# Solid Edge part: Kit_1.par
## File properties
Sűrűség: 0,000 kg/m^3
Pontosság: 0,990
Author: bmolnar
Last saved by: bmolnar
Revision: 77
Username: bmolnar
Dokumentum tartalom típus: 0
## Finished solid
Body 1: solid body, 30 faces, 47 edges, 37 vertices.
  Faces by surface: plane 12, cylinder 10, cone 6, torus 2
  Edges by curve: circle 29, line 18
Bounding box of the edges (mm; curved faces can reach further): 29.400 x 28.800 x 3.400, from (-14.6832, -13.45, 54.8) to (14.7168, 15.3498, 58.2).
Cylindrical faces by radius (mm): R1 x2, R1.8 x2, R5.24 x1, R5.7 x1, R8.75 x1, R12.9833 x1, R13.45 x1, R14.7 x1
Conical faces (half-angle, radius in mm at the cone's reference point): 14 deg R5.12 x1, 14 deg R5.3801 x1, 17 deg R5.12 x1, 45 deg R5.85 x1, 45 deg R8.5 x1, 87 deg R5.1371 x1
Toroidal faces (ring radius, tube radius in mm): R5.6606 r0.18 x1, R9.15 r0.4 x1
Planar faces by outward normal: +z 6, -z 2, oblique 4
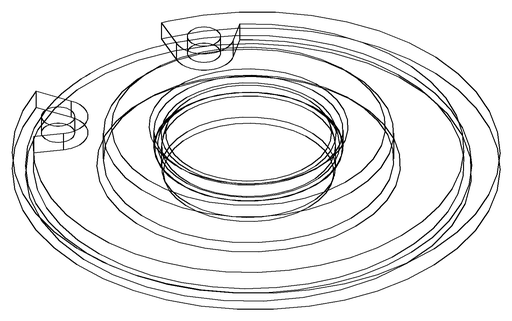
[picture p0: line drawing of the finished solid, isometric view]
